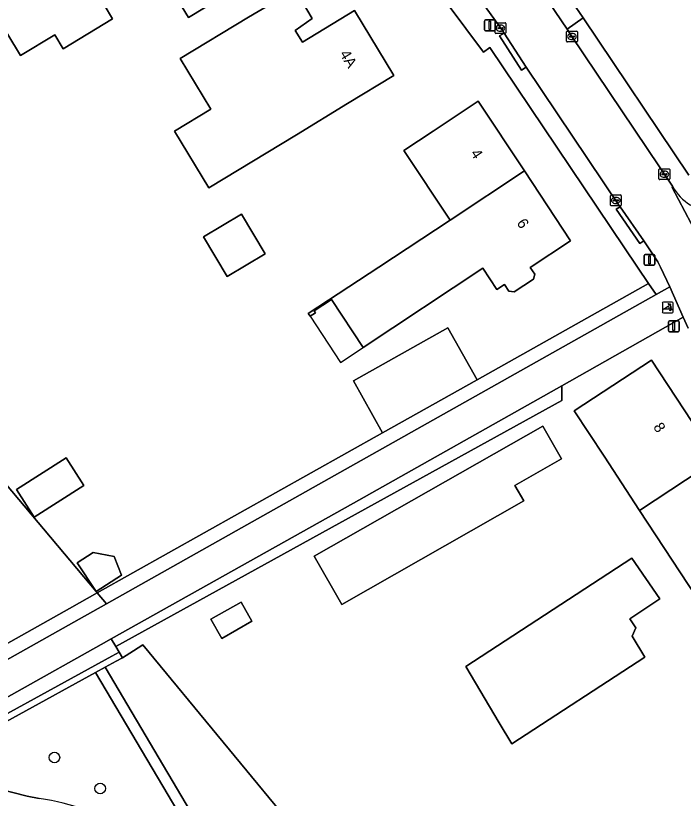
# Model space of a CAD drawing. Extents: x 157320 to 158835, y 386650 to 388491.
# Drawn here: x 157625 to 157686.5, y 387451 to 387523.2 of the extents above; entities that cross this region are included whole.
import ezdxf

# ---------------------------------------------------------------- set-up
doc = ezdxf.new("R2010")
doc.units = 0
for name, color, linetype in [('IMGEO_Afsluitpaal', 7, 'Continuous'), ('IMGEO_Boom', 7, 'Continuous'), ('IMGEO_Erf', 7, 'Continuous'), ('IMGEO_Fietspad_gesloten', 7, 'Continuous'), ('IMGEO_Groenvoorziening', 7, 'Continuous'), ('IMGEO_Haag', 7, 'Continuous'), ('IMGEO_Kolk', 7, 'Continuous'), ('IMGEO_Lichtmast', 7, 'Continuous'), ('IMGEO_Pand', 7, 'Continuous'), ('IMGEO_Pand_nummerreeks', 7, 'Continuous'), ('IMGEO_Pand_overbouw', 7, 'Continuous'), ('IMGEO_Poller', 7, 'Continuous'), ('IMGEO_Rijbaan_lokaal_open', 7, 'Continuous'), ('IMGEO_Voetpad_halfverhard', 7, 'Continuous'), ('IMGEO_Voetpad_open', 7, 'Continuous')]:
    doc.layers.add(name, color=color, linetype=linetype)

msp = doc.modelspace()

# ---------------------------------------------------------------- linework, layer by layer
at = {"layer": 'IMGEO_Afsluitpaal'}
for p, q in [((157685.112, 387494.144), (157685.112, 387494.944)), ((157685.112, 387494.944), (157685.112, 387494.144)), ((157685.212, 387495.044), (157686.002, 387495.044)), ((157686.002, 387495.044), (157685.212, 387495.044)), ((157686.102, 387494.944), (157686.102, 387494.144)), ((157686.102, 387494.144), (157686.102, 387494.944)), ((157686.002, 387494.044), (157685.212, 387494.044)), ((157685.212, 387494.044), (157686.002, 387494.044))]:
    msp.add_line(p, q, dxfattribs=at)
msp.add_lwpolyline([(157685.532, 387494.919), (157685.682, 387494.919), (157685.682, 387494.169), (157685.532, 387494.169), (157685.532, 387494.919)], dxfattribs=at)
for centre, start, end in [((157685.212, 387494.944), 90, 180), ((157685.212, 387494.944), 90, 180), ((157686.002, 387494.944), 0, 90), ((157686.002, 387494.944), 360, 90), ((157685.212, 387494.144), 180, 270), ((157685.212, 387494.144), 180, 270), ((157686.002, 387494.144), 270, 0), ((157686.002, 387494.144), 270, 0)]:
    msp.add_arc(centre, 0.1, start, end, dxfattribs=at)
at = {"layer": 'IMGEO_Boom'}
for centre in [(157628.542, 387454.806), (157632.761, 387451.953)]:
    msp.add_circle(centre, 0.489, dxfattribs=at)
at = {"layer": 'IMGEO_Erf'}
for points in [[(157692.204, 387591.043), (157667.746, 387555.368), (157667.388, 387554.848), (157669.123, 387550.99), (157668.171, 387550.405), (157674.116, 387541.126), (157667.475, 387536.826), (157669.066, 387534.732), (157670.09, 387533.368), (157673.191, 387528.895), (157677.271, 387522.958), (157686.994, 387508.47)], [(157578.677, 387533.351), (157589.022, 387521.485), (157585.187, 387519.238), (157585.374, 387519.338), (157585.745, 387518.605), (157586.649, 387516.822), (157587.12, 387517.048), (157591.371, 387519.091), (157603.527, 387504.64), (157607.341, 387500), (157624.626, 387479.366), (157632.385, 387470.107), (157632.495, 387469.976), (157658.768, 387484.732), (157656.085, 387489.51), (157664.795, 387494.402), (157667.478, 387489.624), (157683.28, 387498.499), (157682.27, 387500), (157668.661, 387520.225), (157668.072, 387519.813), (157664.817, 387524.172)], [(157686.922, 387494.383), (157686.466, 387495.373), (157675.285, 387489.072), (157675.287, 387487.712), (157634.213, 387465.047), (157634.513, 387464.525), (157634.812, 387464.005), (157635.835, 387464.645), (157636.69, 387465.18), (157658.884, 387438.296), (157671.22, 387444.36), (157672.256, 387443.31), (157677.124, 387437.81), (157695.387, 387417.176)]]:
    msp.add_lwpolyline(points, dxfattribs=at)
for points in [[(157638.7, 387533.275), (157640.531, 387530.281), (157645.026, 387533.009), (157646.584, 387533.954), (157649.902, 387528.487), (157645.627, 387525.893), (157640.88, 387523.011), (157638.805, 387526.43), (157635.982, 387524.717), (157635.458, 387525.58), (157633.112, 387524.156), (157633.89, 387522.874), (157629.359, 387520.124), (157628.581, 387521.406), (157625.418, 387519.486), (157622.876, 387523.676), (157634.424, 387530.684)], [(157650.708, 387525.581), (157652.299, 387522.916), (157650.736, 387521.813), (157651.385, 387520.73), (157656.192, 387523.646), (157659.816, 387517.661), (157655.539, 387515.071), (157650.84, 387512.186), (157642.754, 387507.317), (157639.604, 387512.534), (157642.949, 387514.551), (157640.138, 387519.214), (157646.415, 387523.019)], [(157667.599, 387515.279), (157671.843, 387508.868), (157676.106, 387502.429), (157672.379, 387499.961), (157672.794, 387499.337), (157672.682, 387498.892), (157670.899, 387497.711), (157670.413, 387497.773), (157670.005, 387498.389), (157669.307, 387497.927), (157668.006, 387499.892), (157656.992, 387492.601), (157654.067, 387497.021), (157652.474, 387495.967), (157652.585, 387495.8), (157652.092, 387495.473), (157651.926, 387495.723), (157658.419, 387500), (157664.993, 387504.33), (157660.748, 387510.742), (157663.431, 387512.519)], [(157644.452, 387499.148), (157642.29, 387502.799), (157645.787, 387504.869), (157647.949, 387501.218)], [(157679.184, 387482.571), (157676.439, 387486.75), (157683.557, 387491.425), (157689.578, 387482.257), (157695.599, 387473.09), (157691.42, 387470.346), (157688.481, 387468.415), (157682.46, 387477.582)], [(157655.014, 387468.913), (157652.486, 387473.358), (157673.549, 387485.336), (157675.266, 387482.316), (157670.978, 387479.878), (157671.788, 387478.452)], [(157629.627, 387482.434), (157631.262, 387479.872), (157626.687, 387476.954), (157625.052, 387479.516)], [(157632.385, 387470.107), (157630.627, 387472.746), (157632.114, 387473.69), (157634.053, 387473.34), (157634.713, 387471.621)], [(157670.681, 387456.055), (157669.525, 387458.001), (157666.439, 387463.196), (157681.745, 387473.168), (157684.318, 387469.436), (157681.567, 387467.595), (157682.109, 387466.767), (157681.772, 387465.993), (157682.928, 387464.047)], [(157643.965, 387465.787), (157642.962, 387467.55), (157645.735, 387469.127), (157646.738, 387467.364)]]:
    msp.add_lwpolyline(points, close=True, dxfattribs=at)
at = {"layer": 'IMGEO_Fietspad_gesloten'}
msp.add_lwpolyline([(157617.283, 387456.503), (157632.863, 387465.235), (157633.78, 387465.749), (157656.103, 387478.261), (157675.285, 387489.072), (157686.466, 387495.373), (157685.244, 387498.189), (157683.971, 387497.472), (157647.25, 387476.796), (157633.337, 387468.972), (157630.816, 387467.555), (157615.834, 387459.13)], dxfattribs=at)
at = {"layer": 'IMGEO_Groenvoorziening'}
for points in [[(157607.341, 387500), (157603.527, 387504.64), (157591.371, 387519.091), (157587.12, 387517.048), (157586.649, 387516.822), (157614.175, 387462.502), (157615.095, 387461.33), (157616.923, 387461.23), (157629.943, 387468.543), (157632.495, 387469.976), (157632.385, 387470.107), (157624.626, 387479.366)], [(157633.337, 387468.972), (157647.25, 387476.796), (157683.971, 387497.472), (157683.28, 387498.499), (157667.478, 387489.624), (157658.768, 387484.732), (157632.495, 387469.976)], [(157634.213, 387465.047), (157675.287, 387487.712), (157675.285, 387489.072), (157656.103, 387478.261), (157633.78, 387465.749)], [(157614.175, 387462.502), (157614.814, 387460.922), (157615.834, 387459.13), (157630.816, 387467.555), (157633.337, 387468.972), (157632.495, 387469.976), (157629.943, 387468.543), (157616.923, 387461.23), (157615.095, 387461.33)], [(157617.283, 387456.503), (157617.926, 387455.422), (157633.824, 387464.147), (157634.513, 387464.525), (157634.213, 387465.047), (157633.78, 387465.749), (157632.863, 387465.235)], [(157672.256, 387443.31), (157671.22, 387444.36), (157658.884, 387438.296), (157636.69, 387465.18), (157635.835, 387464.645), (157634.812, 387464.005), (157634.231, 387463.686), (157633.203, 387463.122), (157653.441, 387428.946), (157661.44, 387432.867), (157669.714, 387436.922), (157689.444, 387414.056), (157694.481, 387416.709), (157676.322, 387437.108), (157677.124, 387437.81)], [(157617.926, 387455.422), (157618.233, 387454.906), (157632.327, 387462.641), (157633.203, 387463.122), (157634.231, 387463.686), (157634.812, 387464.005), (157634.513, 387464.525), (157633.824, 387464.147)], [(157633.203, 387463.122), (157632.327, 387462.641), (157653.211, 387427.372), (157654.077, 387427.873), (157653.441, 387428.946)]]:
    msp.add_lwpolyline(points, close=True, dxfattribs=at)
for points in [[(157669.714, 387436.922), (157661.44, 387432.867), (157653.441, 387428.946), (157654.077, 387427.873), (157653.211, 387427.372), (157632.327, 387462.641), (157618.233, 387454.906), (157618.59, 387454.28)], [(157620.354, 387452.803), (157623.642, 387451.854), (157624.715, 387451.578), (157626.024, 387451.256), (157627.148, 387451.046)]]:
    msp.add_lwpolyline(points, dxfattribs=at)
msp.add_arc((157622.881, 387424.804), 26.587, 61.31213, 80.76515, dxfattribs=at)
at = {"layer": 'IMGEO_Haag'}
for points in [[(157632.327, 387462.641), (157633.203, 387463.122), (157634.231, 387463.686), (157634.812, 387464.005), (157634.513, 387464.525), (157633.824, 387464.147), (157617.926, 387455.422), (157618.233, 387454.906)], [(157633.203, 387463.122), (157632.327, 387462.641), (157653.211, 387427.372), (157654.077, 387427.873), (157653.441, 387428.946)]]:
    msp.add_lwpolyline(points, close=True, dxfattribs=at)
at = {"layer": 'IMGEO_Kolk'}
for p, q in [((157669.136, 387521.592), (157669.136, 387522.444)), ((157669.211, 387522.518), (157670.063, 387522.518)), ((157669.395, 387522.012), (157669.395, 387522.024)), ((157669.833, 387521.975), (157669.435, 387521.975)), ((157669.438, 387522.061), (157669.836, 387522.061)), ((157669.624, 387522.298), (157669.649, 387522.298)), ((157669.879, 387522.024), (157669.879, 387522.012)), ((157670.137, 387522.444), (157670.137, 387521.592)), ((157670.063, 387521.518), (157669.211, 387521.518)), ((157669.647, 387521.738), (157669.622, 387521.738)), ((157675.727, 387520.819), (157675.727, 387521.671)), ((157675.802, 387521.745), (157676.654, 387521.745)), ((157675.986, 387521.239), (157675.986, 387521.251)), ((157676.029, 387521.288), (157676.427, 387521.288)), ((157676.215, 387521.525), (157676.24, 387521.525)), ((157676.47, 387521.251), (157676.47, 387521.239)), ((157676.728, 387521.671), (157676.728, 387520.819)), ((157676.654, 387520.745), (157675.802, 387520.745)), ((157676.424, 387521.202), (157676.026, 387521.202)), ((157676.238, 387520.965), (157676.213, 387520.965)), ((157684.241, 387508.131), (157684.241, 387508.983)), ((157684.316, 387509.057), (157685.168, 387509.057)), ((157685.242, 387508.983), (157685.242, 387508.131)), ((157684.5, 387508.551), (157684.5, 387508.563)), ((157684.938, 387508.514), (157684.54, 387508.514)), ((157684.543, 387508.6), (157684.941, 387508.6)), ((157684.752, 387508.277), (157684.727, 387508.277)), ((157684.729, 387508.837), (157684.754, 387508.837)), ((157684.984, 387508.563), (157684.984, 387508.551)), ((157685.168, 387508.057), (157684.316, 387508.057)), ((157679.771, 387505.717), (157679.771, 387506.569)), ((157679.846, 387506.643), (157680.698, 387506.643)), ((157680.03, 387506.137), (157680.03, 387506.149)), ((157680.468, 387506.1), (157680.07, 387506.1)), ((157680.073, 387506.186), (157680.471, 387506.186)), ((157680.259, 387506.423), (157680.284, 387506.423)), ((157680.514, 387506.149), (157680.514, 387506.137)), ((157680.772, 387506.569), (157680.772, 387505.717)), ((157680.698, 387505.643), (157679.846, 387505.643)), ((157680.282, 387505.863), (157680.257, 387505.863))]:
    msp.add_line(p, q, dxfattribs=at)
for points in [[(157669.136, 387521.592), (157669.136, 387522.444)], [(157669.211, 387522.518), (157670.063, 387522.518)], [(157670.137, 387522.444), (157670.137, 387521.592)], [(157670.063, 387521.518), (157669.211, 387521.518)], [(157675.727, 387520.819), (157675.727, 387521.671)], [(157675.802, 387521.745), (157676.654, 387521.745)], [(157676.728, 387521.671), (157676.728, 387520.819)], [(157676.654, 387520.745), (157675.802, 387520.745)], [(157684.241, 387508.131), (157684.241, 387508.983)], [(157684.316, 387509.057), (157685.168, 387509.057)], [(157685.242, 387508.983), (157685.242, 387508.131)], [(157685.168, 387508.057), (157684.316, 387508.057)], [(157679.771, 387505.717), (157679.771, 387506.569)], [(157679.846, 387506.643), (157680.698, 387506.643)], [(157680.772, 387506.569), (157680.772, 387505.717)], [(157680.698, 387505.643), (157679.846, 387505.643)]]:
    msp.add_lwpolyline(points, dxfattribs=at)
for centre, radius, start, end in [((157669.213, 387522.442), 0.0765, 91.55205, 178.44795), ((157669.213, 387522.442), 0.0765, 91.55205, 178.44795), ((157669.435, 387522.021), 0.0403, 85.87752, 175.75265), ((157669.432, 387522.011), 0.0366, 178.93798, 274.71019), ((157669.836, 387522.018), 0.043, 264.86636, 352.45326), ((157669.84, 387522.023), 0.0386, 1.73085, 96.63898), ((157670.061, 387522.442), 0.0765, 1.55205, 88.44795), ((157670.061, 387522.442), 0.0765, 1.55205, 88.44795), ((157669.213, 387521.594), 0.0765, 181.55205, 268.44795), ((157669.213, 387521.594), 0.0765, 181.55205, 268.44795), ((157670.061, 387521.594), 0.0765, 271.55205, 358.44795), ((157670.061, 387521.594), 0.0765, 271.55205, 358.44795), ((157675.804, 387521.669), 0.0765, 91.55205, 178.44795), ((157675.804, 387521.669), 0.0765, 91.55205, 178.44795), ((157676.026, 387521.248), 0.0403, 85.87752, 175.75265), ((157676.023, 387521.238), 0.0366, 178.93798, 274.71019), ((157676.427, 387521.245), 0.043, 264.86636, 352.45326), ((157676.431, 387521.25), 0.0386, 1.73085, 96.63898), ((157676.652, 387521.669), 0.0765, 1.55205, 88.44795), ((157676.652, 387521.669), 0.0765, 1.55205, 88.44795), ((157675.804, 387520.821), 0.0765, 181.55205, 268.44795), ((157675.804, 387520.821), 0.0765, 181.55205, 268.44795), ((157676.652, 387520.821), 0.0765, 271.55205, 358.44795), ((157676.652, 387520.821), 0.0765, 271.55205, 358.44795), ((157684.318, 387508.981), 0.0765, 91.55205, 178.44795), ((157684.318, 387508.981), 0.0765, 91.55205, 178.44795), ((157685.166, 387508.981), 0.0765, 1.55205, 88.44795), ((157685.166, 387508.981), 0.0765, 1.55205, 88.44795), ((157684.54, 387508.56), 0.0403, 85.87752, 175.75265), ((157684.537, 387508.55), 0.0366, 178.93798, 274.71019), ((157684.941, 387508.557), 0.043, 264.86636, 352.45326), ((157684.945, 387508.562), 0.0386, 1.73085, 96.63898), ((157684.318, 387508.133), 0.0765, 181.55205, 268.44795), ((157684.318, 387508.133), 0.0765, 181.55205, 268.44795), ((157685.166, 387508.133), 0.0765, 271.55205, 358.44795), ((157685.166, 387508.133), 0.0765, 271.55205, 358.44795), ((157679.848, 387506.567), 0.0765, 91.55205, 178.44795), ((157679.848, 387506.567), 0.0765, 91.55205, 178.44795), ((157680.07, 387506.146), 0.0403, 85.87752, 175.75265), ((157680.067, 387506.136), 0.0366, 178.93798, 274.71019), ((157680.471, 387506.143), 0.043, 264.86636, 352.45326), ((157680.475, 387506.148), 0.0386, 1.73085, 96.63898), ((157680.696, 387506.567), 0.0765, 1.55205, 88.44795), ((157680.696, 387506.567), 0.0765, 1.55205, 88.44795), ((157679.848, 387505.719), 0.0765, 181.55205, 268.44795), ((157679.848, 387505.719), 0.0765, 181.55205, 268.44795), ((157680.696, 387505.719), 0.0765, 271.55205, 358.44795), ((157680.696, 387505.719), 0.0765, 271.55205, 358.44795)]:
    msp.add_arc(centre, radius, start, end, dxfattribs=at)
for centre, major_axis, ratio, start_param, end_param in [((157669.623, 387522.018), (-0.387, 0.002), 0.722429, 4.712389, 7.853982), ((157669.648, 387522.018), (-0.39, 0.002), 0.717154, 1.570796, 4.712389), ((157676.214, 387521.245), (-0.387, 0.002), 0.722429, 4.712389, 7.853982), ((157676.239, 387521.245), (-0.39, 0.002), 0.717154, 1.570796, 4.712389), ((157684.728, 387508.557), (-0.387, 0.002), 0.722429, 4.712389, 7.853982), ((157684.753, 387508.557), (-0.39, 0.002), 0.717154, 1.570796, 4.712389), ((157680.258, 387506.143), (-0.387, 0.002), 0.722429, 4.712389, 7.853982), ((157680.283, 387506.143), (-0.39, 0.002), 0.717154, 1.570796, 4.712389)]:
    msp.add_ellipse(centre, major_axis=major_axis, ratio=ratio, start_param=start_param, end_param=end_param, dxfattribs=at)
at = {"layer": 'IMGEO_Lichtmast'}
for p, q in [((157668.165, 387521.876), (157668.165, 387522.676)), ((157668.165, 387522.676), (157668.165, 387521.876)), ((157668.265, 387522.776), (157669.055, 387522.776)), ((157669.055, 387522.776), (157668.265, 387522.776)), ((157669.155, 387522.676), (157669.155, 387521.876)), ((157669.155, 387521.876), (157669.155, 387522.676)), ((157669.055, 387521.776), (157668.265, 387521.776)), ((157668.265, 387521.776), (157669.055, 387521.776)), ((157682.874, 387500.272), (157682.874, 387501.072)), ((157682.874, 387501.072), (157682.874, 387500.272)), ((157682.974, 387501.172), (157683.764, 387501.172)), ((157683.764, 387501.172), (157682.974, 387501.172)), ((157683.864, 387501.072), (157683.864, 387500.272)), ((157683.864, 387500.272), (157683.864, 387501.072)), ((157683.764, 387500.172), (157682.974, 387500.172)), ((157682.974, 387500.172), (157683.764, 387500.172))]:
    msp.add_line(p, q, dxfattribs=at)
for points in [[(157668.585, 387522.651), (157668.735, 387522.651), (157668.735, 387521.901), (157668.585, 387521.901), (157668.585, 387522.651)], [(157683.294, 387501.047), (157683.444, 387501.047), (157683.444, 387500.297), (157683.294, 387500.297), (157683.294, 387501.047)]]:
    msp.add_lwpolyline(points, dxfattribs=at)
for centre, start, end in [((157668.265, 387522.676), 90, 180), ((157668.265, 387522.676), 90, 180), ((157669.055, 387522.676), 0, 90), ((157669.055, 387522.676), 360, 90), ((157668.265, 387521.876), 180, 270), ((157668.265, 387521.876), 180, 270), ((157669.055, 387521.876), 270, 0), ((157669.055, 387521.876), 270, 0), ((157682.974, 387501.072), 90, 180), ((157682.974, 387501.072), 90, 180), ((157683.764, 387501.072), 0, 90), ((157683.764, 387501.072), 360, 90), ((157682.974, 387500.272), 180, 270), ((157682.974, 387500.272), 180, 270), ((157683.764, 387500.272), 270, 0), ((157683.764, 387500.272), 270, 0)]:
    msp.add_arc(centre, 0.1, start, end, dxfattribs=at)
at = {"layer": 'IMGEO_Pand'}
for points in [[(157634.424, 387530.684), (157622.876, 387523.676), (157625.418, 387519.486), (157628.581, 387521.406), (157629.359, 387520.124), (157633.89, 387522.874), (157633.112, 387524.156), (157635.458, 387525.58), (157635.982, 387524.717), (157638.805, 387526.43), (157640.88, 387523.011), (157645.627, 387525.893), (157649.902, 387528.487), (157646.584, 387533.954), (157645.026, 387533.009), (157640.531, 387530.281), (157638.7, 387533.275)], [(157656.192, 387523.646), (157651.385, 387520.73), (157650.736, 387521.813), (157652.299, 387522.916), (157650.708, 387525.581), (157646.415, 387523.019), (157640.138, 387519.214), (157642.949, 387514.551), (157639.604, 387512.534), (157642.754, 387507.317), (157650.84, 387512.186), (157655.539, 387515.071), (157659.816, 387517.661)], [(157671.843, 387508.868), (157667.599, 387515.279), (157663.431, 387512.519), (157660.748, 387510.742), (157664.993, 387504.33)], [(157671.843, 387508.868), (157664.993, 387504.33), (157658.419, 387500), (157651.926, 387495.723), (157652.092, 387495.473), (157652.585, 387495.8), (157652.474, 387495.967), (157654.067, 387497.021), (157656.992, 387492.601), (157668.006, 387499.892), (157669.307, 387497.927), (157670.005, 387498.389), (157670.413, 387497.773), (157670.899, 387497.711), (157672.682, 387498.892), (157672.794, 387499.337), (157672.379, 387499.961), (157676.106, 387502.429)], [(157644.452, 387499.148), (157647.949, 387501.218), (157645.787, 387504.869), (157642.29, 387502.799)], [(157658.768, 387484.732), (157667.478, 387489.624), (157664.795, 387494.402), (157656.085, 387489.51)], [(157689.578, 387482.257), (157683.557, 387491.425), (157676.439, 387486.75), (157679.184, 387482.571), (157682.46, 387477.582)], [(157655.014, 387468.913), (157671.788, 387478.452), (157670.978, 387479.878), (157675.266, 387482.316), (157673.549, 387485.336), (157652.486, 387473.358)], [(157625.052, 387479.516), (157626.687, 387476.954), (157631.262, 387479.872), (157629.627, 387482.434)], [(157689.578, 387482.257), (157682.46, 387477.582), (157688.481, 387468.415), (157691.42, 387470.346), (157695.599, 387473.09)], [(157634.053, 387473.34), (157632.114, 387473.69), (157630.627, 387472.746), (157632.385, 387470.107), (157634.713, 387471.621)], [(157669.525, 387458.001), (157670.681, 387456.055), (157682.928, 387464.047), (157681.772, 387465.993), (157682.109, 387466.767), (157681.567, 387467.595), (157684.318, 387469.436), (157681.745, 387473.168), (157666.439, 387463.196)], [(157643.965, 387465.787), (157646.738, 387467.364), (157645.735, 387469.127), (157642.962, 387467.55)]]:
    msp.add_lwpolyline(points, close=True, dxfattribs=at)
at = {"layer": 'IMGEO_Pand_overbouw'}
msp.add_lwpolyline([(157652.092, 387495.473), (157654.907, 387491.22), (157656.992, 387492.601), (157654.067, 387497.021), (157652.474, 387495.967), (157652.585, 387495.8)], close=True, dxfattribs=at)
at = {"layer": 'IMGEO_Poller'}
for p, q in [((157685.455, 387496.776), (157684.647, 387496.776)), ((157685.455, 387496.776), (157684.647, 387496.776)), ((157684.553, 387496.681), (157684.553, 387495.874)), ((157684.553, 387496.681), (157684.553, 387495.874)), ((157685.549, 387495.874), (157685.549, 387496.681)), ((157685.549, 387495.874), (157685.549, 387496.681)), ((157684.647, 387495.779), (157685.455, 387495.779)), ((157684.647, 387495.779), (157685.455, 387495.779))]:
    msp.add_line(p, q, dxfattribs=at)
for points in [[(157685.188, 387496.132), (157684.675, 387496.132), (157685.105, 387496.407)], [(157685.232, 387496.505), (157685.22, 387496.432), (157685.095, 387496.637)], [(157685.095, 387496.637), (157685.326, 387496.571), (157685.255, 387496.539)], [(157685.248, 387495.96), (157685.314, 387496.191), (157685.344, 387496.123)], [(157685.38, 387496.096), (157685.452, 387496.085), (157685.248, 387495.96)]]:
    msp.add_lwpolyline(points, dxfattribs=at)
for centre, radius, start, end in [((157684.647, 387496.681), 0.0946, 90, 180), ((157684.647, 387496.681), 0.0946, 90, 180), ((157685.455, 387496.681), 0.0946, 0, 90), ((157685.455, 387496.681), 0.0946, 0, 90), ((157684.86, 387496.182), 0.332, 351.32473, 42.4854), ((157684.874, 387496.192), 0.476, 351.75274, 41.16905), ((157684.874, 387496.192), 0.516, 349.35686, 42.29123), ((157684.647, 387495.874), 0.0946, 180, 270), ((157684.647, 387495.874), 0.0946, 180, 270), ((157685.455, 387495.874), 0.0946, 270, 0), ((157685.455, 387495.874), 0.0946, 270, 0)]:
    msp.add_arc(centre, radius, start, end, dxfattribs=at)
at = {"layer": 'IMGEO_Rijbaan_lokaal_open'}
for points in [[(157662.154, 387532.504), (157663.218, 387531.039), (157664.298, 387529.476), (157669.811, 387521.79), (157669.975, 387521.569), (157671.993, 387518.43), (157680.547, 387505.706), (157680.673, 387505.54), (157682.854, 387502.424), (157684.153, 387500.476), (157684.395, 387500), (157685.244, 387498.189), (157686.466, 387495.373), (157686.922, 387494.383)], [(157692.475, 387494.071), (157685.451, 387507.338), (157685.485, 387507.447), (157676.165, 387521.337), (157675.79, 387521.931), (157671.769, 387527.89), (157669.745, 387530.772)], [(157685.485, 387507.447), (157685.451, 387507.338), (157692.475, 387494.071), (157692.652, 387494.004)]]:
    msp.add_lwpolyline(points, dxfattribs=at)
msp.add_arc((157689.415, 387509.598), 4.48, 208.69081, 270.00545, dxfattribs=at)
at = {"layer": 'IMGEO_Voetpad_halfverhard'}
msp.add_lwpolyline([(157627.148, 387451.046), (157626.024, 387451.256), (157624.715, 387451.578), (157623.642, 387451.854), (157620.354, 387452.803)], dxfattribs=at)
msp.add_arc((157622.881, 387424.804), 26.587, 61.31213, 80.76515, dxfattribs=at)
at = {"layer": 'IMGEO_Voetpad_open'}
for points in [[(157664.817, 387524.172), (157668.072, 387519.813), (157668.661, 387520.225), (157682.27, 387500), (157683.28, 387498.499), (157683.971, 387497.472), (157685.244, 387498.189), (157684.395, 387500), (157684.153, 387500.476), (157682.854, 387502.424), (157682.485, 387502.164), (157680.294, 387505.33), (157680.673, 387505.54), (157680.547, 387505.706), (157671.993, 387518.43), (157671.573, 387518.16), (157669.555, 387521.299), (157669.975, 387521.569), (157669.811, 387521.79), (157664.298, 387529.476), (157663.966, 387529.224), (157661.822, 387532.24), (157662.154, 387532.504)], [(157677.271, 387522.958), (157675.79, 387521.931), (157676.165, 387521.337), (157685.485, 387507.447)], [(157686.994, 387508.47), (157677.271, 387522.958)]]:
    msp.add_lwpolyline(points, dxfattribs=at)
for points in [[(157675.79, 387521.931), (157677.271, 387522.958), (157673.191, 387528.895), (157671.769, 387527.89)], [(157669.975, 387521.569), (157669.555, 387521.299), (157671.573, 387518.16), (157671.993, 387518.43)], [(157680.673, 387505.54), (157680.294, 387505.33), (157682.485, 387502.164), (157682.854, 387502.424)]]:
    msp.add_lwpolyline(points, close=True, dxfattribs=at)
msp.add_arc((157689.415, 387509.598), 4.48, 208.69081, 270.00545, dxfattribs=at)

# ---------------------------------------------------------------- texts
at = {"layer": 'IMGEO_Pand_nummerreeks'}
for s, rotation, p in [('4A', 301.19734, (157654.782, 387519.643)), ('4', 303.50636, (157666.839, 387510.486)), ('6', 303.50636, (157671.092, 387504.061)), ('8', 303.29437, (157683.677, 387485.267))]:
    msp.add_text(s, height=1, rotation=rotation, dxfattribs=at).set_placement(p)

doc.saveas('drawing.dxf')
